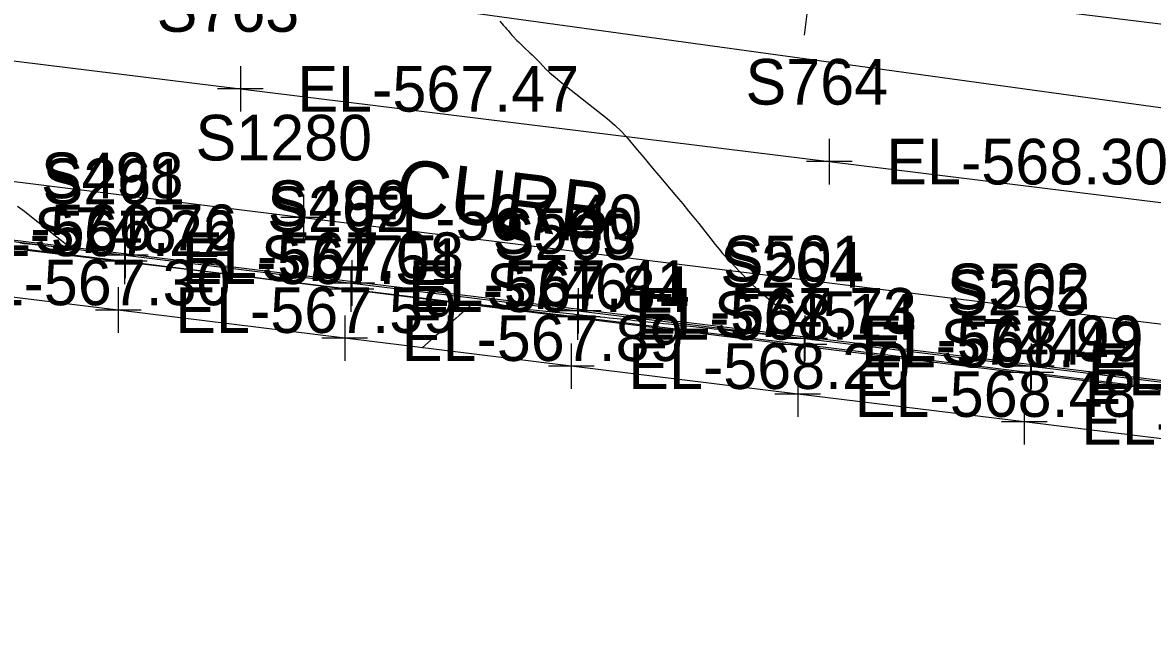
# Model space of a CAD drawing. Extents: x 1724534 to 1727318, y 657156 to 660047.
# Drawn here: x 1725592.4 to 1725691.4, y 658537.5 to 658591.4 of the extents above; entities that cross this region are included whole.
import ezdxf

# ---------------------------------------------------------------- set-up
doc = ezdxf.new("R2010")
doc.units = 0
for name, color, linetype in [('SURVEY - CENTERLINE - Preliminary Text', 7, 'Continuous'), ('SURVEY - CONTOURS - Intermediate with optional Text', 7, 'Continuous'), ('SURVEY - DRAINAGE - Area Shapes', 7, 'Continuous'), ('SURVEY - DRAINAGE - Storm Sewer', 7, 'Continuous'), ('SURVEY - DTM - Breaklines', 7, 'Continuous'), ('SURVEY - DTM - Breaklines - Points - Elevations', 7, 'Continuous'), ('SURVEY - DTM - Breaklines - Points - Locators', 7, 'Continuous'), ('SURVEY - DTM - Breaklines - Points - Numbers', 7, 'Continuous'), ('SURVEY - ROADSIDE BARRIERS - Points - Elevations', 7, 'Continuous'), ('SURVEY - ROADSIDE BARRIERS - Points - Locators', 7, 'Continuous'), ('SURVEY - ROADSIDE BARRIERS - Points - Numbers', 7, 'Continuous'), ('SURVEY - ROADSIDE BARRIERS with Text', 7, 'Continuous'), ('SURVEY - TRAFFIC CONTROL - Pavement Marking - Points - Elevations', 7, 'Continuous'), ('SURVEY - TRAFFIC CONTROL - Pavement Marking - Points - Locators', 7, 'Continuous'), ('SURVEY - TRAFFIC CONTROL - Pavement Marking - Points - Numbers', 7, 'Continuous'), ('SURVEY - TRAFFIC CONTROL - Pavement Marking with Text', 7, 'Continuous'), ('SURVEY - TRANSPORTATION - Features', 7, 'Continuous'), ('SURVEY - TRANSPORTATION - Features - Points - Elevations', 7, 'Continuous'), ('SURVEY - TRANSPORTATION - Features - Points - Locators', 7, 'Continuous'), ('SURVEY - TRANSPORTATION - Features - Points - Numbers', 7, 'Continuous'), ('SURVEY - TRANSPORTATION - Features Text', 7, 'Continuous'), ('SURVEY - TRANSPORTATION - Roads', 7, 'Continuous'), ('SURVEY - TRANSPORTATION - Roads - Points - Elevations', 7, 'Continuous'), ('SURVEY - TRANSPORTATION - Roads - Points - Locators', 7, 'Continuous'), ('SURVEY - TRANSPORTATION - Roads - Points - Numbers', 7, 'Continuous'), ('SURVEY - UTILITIES - Electric (Underground) with Text', 7, 'Continuous')]:
    doc.layers.add(name, color=color, linetype=linetype)

msp = doc.modelspace()

# ---------------------------------------------------------------- linework, layer by layer
at = {"layer": 'SURVEY - CENTERLINE - Preliminary Text'}
msp.add_line((1725661.443, 658595.279), (1725660.839, 658590.316), dxfattribs=at)
at = {"layer": 'SURVEY - CONTOURS - Intermediate with optional Text'}
for points in [[(1725634.164, 658591.543), (1725634.346, 658591.337), (1725634.459, 658591.214), (1725634.668, 658590.995), (1725634.742, 658590.917), (1725634.807, 658590.845), (1725634.862, 658590.781), (1725634.908, 658590.723), (1725635.017, 658590.579), (1725635.068, 658590.515), (1725635.141, 658590.433), (1725635.233, 658590.332), (1725635.347, 658590.213), (1725635.678, 658589.87), (1725635.81, 658589.735), (1725635.959, 658589.588), (1725636.124, 658589.429), (1725636.307, 658589.258), (1725636.815, 658588.785), (1725637.01, 658588.6), (1725637.213, 658588.401), (1725637.425, 658588.187), (1725637.646, 658587.959), (1725638.247, 658587.33), (1725638.553, 658587.039), (1725639.021, 658586.635), (1725639.65, 658586.12), (1725640.441, 658585.494), (1725642.766, 658583.673), (1725643.575, 658583.021), (1725644.257, 658582.43), (1725644.814, 658581.901), (1725645.244, 658581.434), (1725646.224, 658580.269), (1725646.618, 658579.801), (1725647.064, 658579.27), (1725647.563, 658578.677), (1725648.115, 658578.022), (1725649.655, 658576.19), (1725650.211, 658575.526), (1725650.72, 658574.907), (1725651.184, 658574.333), (1725651.603, 658573.805), (1725652.658, 658572.456), (1725653.038, 658571.979), (1725653.384, 658571.558), (1725653.697, 658571.194), (1725653.978, 658570.887), (1725655.211, 658569.586), (1725656.111, 658568.656), (1725656.333, 658568.435), (1725656.614, 658568.173), (1725656.954, 658567.868), (1725657.353, 658567.522), (1725658.497, 658566.541), (1725658.902, 658566.191), (1725659.262, 658565.877), (1725659.575, 658565.6), (1725659.843, 658565.359), (1725660.494, 658564.765), (1725660.708, 658564.57), (1725660.86, 658564.43), (1725660.952, 658564.347), (1725660.983, 658564.319), (1725660.983, 658564.319), (1725660.999, 658564.306), (1725661.047, 658564.266), (1725661.128, 658564.201), (1725661.241, 658564.11), (1725661.842, 658563.623), (1725661.272, 658563.683), (1725661.162, 658563.695), (1725661.079, 658563.704), (1725661.021, 658563.71), (1725660.988, 658563.713), (1725660.937, 658563.719), (1725660.92, 658563.72), (1725660.908, 658563.722), (1725660.9, 658563.722), (1725660.898, 658563.723), (1725660.898, 658563.723), (1725660.898, 658563.723), (1725660.898, 658563.723), (1725660.898, 658563.723), (1725660.898, 658563.723), (1725660.898, 658563.723), (1725660.819, 658563.731), (1725660.583, 658563.756), (1725660.19, 658563.797), (1725659.639, 658563.855), (1725657.961, 658564.032), (1725657.395, 658564.092), (1725656.958, 658564.138), (1725656.649, 658564.17), (1725656.469, 658564.189), (1725656.158, 658564.222), (1725655.989, 658564.239), (1725655.342, 658564.307), (1725654.863, 658564.358), (1725653.449, 658564.506), (1725652.957, 658564.558), (1725652.545, 658564.601), (1725652.211, 658564.636), (1725651.957, 658564.663), (1725651.382, 658564.723), (1725651.14, 658564.748), (1725650.844, 658564.779), (1725650.494, 658564.816), (1725650.091, 658564.858), (1725648.944, 658564.979), (1725648.529, 658565.023), (1725648.141, 658565.063), (1725647.783, 658565.101), (1725647.452, 658565.135), (1725646.61, 658565.223), (1725646.292, 658565.256), (1725645.972, 658565.29), (1725645.649, 658565.324), (1725645.322, 658565.358), (1725644.449, 658565.45), (1725644.11, 658565.485), (1725643.748, 658565.523), (1725643.364, 658565.563), (1725642.957, 658565.606), (1725641.841, 658565.722), (1725641.475, 658565.76), (1725641.213, 658565.787), (1725641.056, 658565.804), (1725641.004, 658565.809), (1725641.004, 658565.809), (1725641.004, 658565.809), (1725641.004, 658565.809), (1725641.004, 658565.809), (1725641.004, 658565.809), (1725641.004, 658565.809), (1725640.976, 658565.812), (1725640.895, 658565.82), (1725640.759, 658565.834), (1725640.57, 658565.854), (1725639.991, 658565.912), (1725639.735, 658565.939), (1725639.401, 658565.973), (1725638.989, 658566.015), (1725638.499, 658566.065), (1725637.087, 658566.21), (1725636.612, 658566.258), (1725636.243, 658566.296), (1725635.983, 658566.323), (1725635.829, 658566.338), (1725635.563, 658566.366), (1725635.409, 658566.381), (1725635.144, 658566.408), (1725634.769, 658566.447), (1725634.284, 658566.496), (1725631.765, 658566.755), (1725631.516, 658566.54), (1725631.461, 658566.492), (1725631.402, 658566.441), (1725631.339, 658566.386), (1725631.273, 658566.329), (1725631.092, 658566.17), (1725630.994, 658566.085), (1725630.838, 658565.949), (1725630.622, 658565.762), (1725630.348, 658565.523), (1725629.538, 658564.82), (1725629.243, 658564.563), (1725628.965, 658564.321), (1725628.705, 658564.093), (1725628.463, 658563.881), (1725627.372, 658562.922)], [(1725591.916, 658575.334), (1725592.512, 658574.882), (1725593.129, 658574.4), (1725594.806, 658573.077), (1725595.362, 658572.638), (1725595.775, 658572.313), (1725596.043, 658572.102), (1725596.168, 658572.006), (1725596.307, 658571.902), (1725596.358, 658571.863), (1725596.405, 658571.827), (1725596.449, 658571.792), (1725596.489, 658571.758), (1725596.668, 658571.607), (1725596.5, 658571.625), (1725596.468, 658571.628), (1725596.443, 658571.63), (1725596.426, 658571.632), (1725596.416, 658571.633), (1725596.398, 658571.635), (1725596.314, 658571.644), (1725596.075, 658571.669), (1725595.681, 658571.71), (1725595.132, 658571.767), (1725593.462, 658571.94), (1725592.899, 658571.998), (1725592.462, 658572.044), (1725592.153, 658572.076)]]:
    msp.add_lwpolyline(points, dxfattribs=at)
at = {"layer": 'SURVEY - DRAINAGE - Area Shapes'}
msp.add_lwpolyline([(1725876.527, 658537.521), (1725880.453, 658568.253), (1725462.782, 658619.36), (1725459.014, 658588.567)], close=True, dxfattribs=at)
at = {"layer": 'SURVEY - DRAINAGE - Storm Sewer'}
msp.add_lwpolyline([(1725899.594, 658555.371), (1725464.565, 658615.304), (1725129.381, 658652.795)], dxfattribs=at)
at = {"layer": 'SURVEY - DTM - Breaklines'}
msp.add_lwpolyline([(1725489.875, 658584.035), (1725509.601, 658581.531), (1725526.033, 658579.596), (1725541.721, 658577.725), (1725561.584, 658575.392), (1725581.434, 658572.95), (1725601.283, 658570.508), (1725621.131, 658568.058), (1725640.981, 658565.625), (1725660.832, 658563.199), (1725680.682, 658560.757), (1725700.532, 658558.327)], dxfattribs=at)
at = {"layer": 'SURVEY - DTM - Breaklines - Points - Locators'}
for p, q in [((1725601.283, 658572.508), (1725601.283, 658568.508)), ((1725603.283, 658570.508), (1725599.283, 658570.508)), ((1725621.131, 658570.058), (1725621.131, 658566.058)), ((1725623.131, 658568.058), (1725619.131, 658568.058)), ((1725640.981, 658567.625), (1725640.981, 658563.625)), ((1725642.981, 658565.625), (1725638.981, 658565.625)), ((1725660.832, 658565.199), (1725660.832, 658561.199)), ((1725662.832, 658563.199), (1725658.832, 658563.199)), ((1725680.682, 658562.757), (1725680.682, 658558.757)), ((1725682.682, 658560.757), (1725678.682, 658560.757))]:
    msp.add_line(p, q, dxfattribs=at)
at = {"layer": 'SURVEY - ROADSIDE BARRIERS - Points - Locators'}
for p, q in [((1725600.739, 658568.219), (1725600.739, 658564.219)), ((1725602.739, 658566.219), (1725598.739, 658566.219)), ((1725620.586, 658565.762), (1725620.586, 658561.762)), ((1725622.586, 658563.762), (1725618.586, 658563.762)), ((1725640.433, 658563.304), (1725640.433, 658559.304)), ((1725642.433, 658561.304), (1725638.433, 658561.304)), ((1725660.282, 658560.858), (1725660.282, 658556.858)), ((1725662.282, 658558.858), (1725658.282, 658558.858)), ((1725680.133, 658558.429), (1725680.133, 658554.429)), ((1725682.133, 658556.429), (1725678.133, 658556.429))]:
    msp.add_line(p, q, dxfattribs=at)
at = {"layer": 'SURVEY - ROADSIDE BARRIERS with Text'}
msp.add_lwpolyline([(1725762.719, 658545.483), (1725760.676, 658546.181), (1725739.67, 658549.027), (1725719.83, 658551.532), (1725699.981, 658553.973), (1725680.133, 658556.429), (1725660.282, 658558.858), (1725640.433, 658561.304), (1725620.586, 658563.762), (1725600.739, 658566.219), (1725580.889, 658568.65), (1725561.039, 658571.092), (1725541.174, 658573.41), (1725539.632, 658573.409), (1725538.14, 658573.134)], dxfattribs=at)
at = {"layer": 'SURVEY - TRAFFIC CONTROL - Pavement Marking - Points - Locators'}
for p, q in [((1725611.44, 658587.624), (1725611.44, 658583.624)), ((1725613.44, 658585.624), (1725609.44, 658585.624)), ((1725663.045, 658581.239), (1725663.045, 658577.239)), ((1725665.045, 658579.239), (1725661.045, 658579.239))]:
    msp.add_line(p, q, dxfattribs=at)
at = {"layer": 'SURVEY - TRAFFIC CONTROL - Pavement Marking with Text'}
msp.add_lwpolyline([(1725507.893, 658598.435), (1725611.44, 658585.624), (1725663.045, 658579.239), (1725732.511, 658570.646), (1725771.433, 658565.831), (1725828.993, 658558.789), (1725876.604, 658552.91), (1725911.384, 658548.615)], dxfattribs=at)
at = {"layer": 'SURVEY - TRANSPORTATION - Features'}
msp.add_lwpolyline([(1725489.947, 658584.602), (1725509.681, 658582.097), (1725524.934, 658580.3), (1725526.112, 658580.162), (1725541.793, 658578.292), (1725561.649, 658575.907), (1725581.5, 658573.471), (1725601.349, 658571.032), (1725621.199, 658568.593), (1725641.048, 658566.157), (1725660.9, 658563.739), (1725680.75, 658561.297), (1725700.601, 658558.867)], dxfattribs=at)
at = {"layer": 'SURVEY - TRANSPORTATION - Features - Points - Locators'}
for p, q in [((1725601.349, 658573.032), (1725601.349, 658569.032)), ((1725603.349, 658571.032), (1725599.349, 658571.032)), ((1725621.199, 658570.593), (1725621.199, 658566.593)), ((1725623.199, 658568.593), (1725619.199, 658568.593)), ((1725641.048, 658568.157), (1725641.048, 658564.157)), ((1725643.048, 658566.157), (1725639.048, 658566.157)), ((1725660.9, 658565.739), (1725660.9, 658561.739)), ((1725662.9, 658563.739), (1725658.9, 658563.739)), ((1725680.75, 658563.297), (1725680.75, 658559.297)), ((1725682.75, 658561.297), (1725678.75, 658561.297))]:
    msp.add_line(p, q, dxfattribs=at)
at = {"layer": 'SURVEY - TRANSPORTATION - Roads'}
msp.add_lwpolyline([(1725460.854, 658593.916), (1725508.47, 658587.877), (1725514.425, 658587.132), (1725525.683, 658585.724), (1725547.511, 658582.986), (1725616.971, 658574.343), (1725730.092, 658560.27)], dxfattribs=at)
at = {"layer": 'SURVEY - TRANSPORTATION - Roads - Points - Locators'}
for p, q in [((1725616.971, 658576.343), (1725616.971, 658572.343)), ((1725618.971, 658574.343), (1725614.971, 658574.343))]:
    msp.add_line(p, q, dxfattribs=at)
at = {"layer": 'SURVEY - UTILITIES - Electric (Underground) with Text'}
msp.add_lwpolyline([(1725505.901, 658581.192), (1725559.522, 658575.408), (1725608.231, 658569.636), (1725663.449, 658562.739), (1725716.937, 658556.185), (1725775.83, 658548.079)], dxfattribs=at)

# ---------------------------------------------------------------- texts
at = {"layer": 'SURVEY - DTM - Breaklines - Points - Elevations'}
for s, p in [('EL-567.22', (1725586.434, 658570.95)), ('EL-567.51', (1725606.283, 658568.508)), ('EL-567.84', (1725626.131, 658566.058)), ('EL-568.14', (1725645.981, 658563.625)), ('EL-568.42', (1725665.832, 658561.199)), ('EL-568.70', (1725685.682, 658558.757))]:
    msp.add_text(s, height=4, dxfattribs=at).set_placement(p)
at = {"layer": 'SURVEY - DTM - Breaklines - Points - Numbers'}
for s, p in [('S261', (1725594.105, 658575.508)), ('S262', (1725613.795, 658573.058)), ('S263', (1725633.645, 658570.625)), ('S264', (1725653.496, 658568.199)), ('S265', (1725673.346, 658565.757))]:
    msp.add_text(s, height=4, dxfattribs=at).set_placement(p)
at = {"layer": 'SURVEY - ROADSIDE BARRIERS - Points - Elevations'}
for s, p in [('EL-567.30', (1725585.889, 658566.65)), ('EL-567.59', (1725605.739, 658564.219)), ('EL-567.89', (1725625.586, 658561.762)), ('EL-568.20', (1725645.433, 658559.304)), ('EL-568.48', (1725665.282, 658556.858)), ('EL-568.77', (1725685.133, 658554.429))]:
    msp.add_text(s, height=4, dxfattribs=at).set_placement(p)
at = {"layer": 'SURVEY - ROADSIDE BARRIERS - Points - Numbers'}
for s, p in [('S748', (1725593.356, 658571.219)), ('S747', (1725613.25, 658568.762)), ('S746', (1725632.987, 658566.304)), ('S745', (1725652.946, 658563.858)), ('S744', (1725672.797, 658561.429))]:
    msp.add_text(s, height=4, dxfattribs=at).set_placement(p)
at = {"layer": 'SURVEY - TRAFFIC CONTROL - Pavement Marking - Points - Elevations'}
for s, p in [('EL-567.47', (1725616.44, 658583.624)), ('EL-568.30', (1725668.045, 658577.239))]:
    msp.add_text(s, height=4, dxfattribs=at).set_placement(p)
at = {"layer": 'SURVEY - TRAFFIC CONTROL - Pavement Marking - Points - Numbers'}
for s, p in [('S763', (1725604.104, 658590.624)), ('S764', (1725655.709, 658584.239))]:
    msp.add_text(s, height=4, dxfattribs=at).set_placement(p)
at = {"layer": 'SURVEY - TRANSPORTATION - Features - Points - Elevations'}
for s, p in [('EL-566.76', (1725586.5, 658571.471)), ('EL-567.08', (1725606.349, 658569.032)), ('EL-567.41', (1725626.199, 658566.593)), ('EL-567.73', (1725646.048, 658564.157)), ('EL-567.99', (1725665.9, 658561.739)), ('EL-568.26', (1725685.75, 658559.297))]:
    msp.add_text(s, height=4, dxfattribs=at).set_placement(p)
at = {"layer": 'SURVEY - TRANSPORTATION - Features - Points - Numbers'}
for s, p in [('S498', (1725593.966, 658576.032)), ('S499', (1725613.847, 658573.593)), ('S500', (1725633.539, 658571.157)), ('S501', (1725653.722, 658568.739)), ('S502', (1725673.414, 658566.297))]:
    msp.add_text(s, height=4, dxfattribs=at).set_placement(p)
at = {"layer": 'SURVEY - TRANSPORTATION - Features Text'}
msp.add_text('CURB', height=5, rotation=353.0555, dxfattribs=at).set_placement((1725624.793, 658574.579))
at = {"layer": 'SURVEY - TRANSPORTATION - Roads - Points - Elevations'}
msp.add_text('EL-567.40', height=4, dxfattribs=at).set_placement((1725621.971, 658572.343))
at = {"layer": 'SURVEY - TRANSPORTATION - Roads - Points - Numbers'}
msp.add_text('S1280', height=4, dxfattribs=at).set_placement((1725607.51, 658579.343))

doc.saveas('drawing.dxf')
